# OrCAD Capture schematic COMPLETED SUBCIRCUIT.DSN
size A
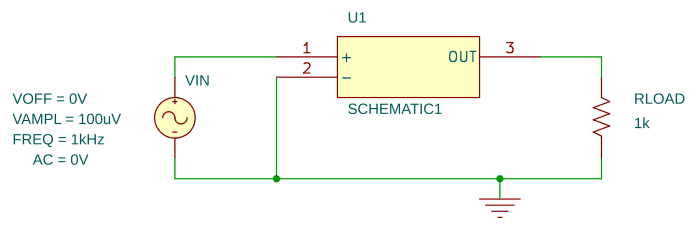
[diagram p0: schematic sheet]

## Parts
RLOAD  1k  [AX/RC05]
U1  SCHEMATIC1
VIN  VSIN

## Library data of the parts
RLOAD = R
U1 = SCHEMATIC1
VIN = VSIN: AC: 0V; FREQ: 1kHz; VAMPL: 100uV; VOFF: 0V

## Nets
0: RLOAD.1 U1.2(-) VIN.2(-)
N00085: RLOAD.2 U1.3(OUT)
N00159: U1.1(+) VIN.1(+)
